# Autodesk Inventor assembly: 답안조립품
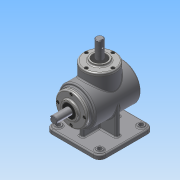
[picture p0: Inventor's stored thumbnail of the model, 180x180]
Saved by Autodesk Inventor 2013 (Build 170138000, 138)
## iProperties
Created: 2015-07
Part Number: 답안조립품
Document SubType Name: Assembly
Designer: ST1
Author: ST1
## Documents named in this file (14)
- C:\Users\ST1\Desktop\450705V1015\답안조립품.iam
- C:\Users\ST1\Desktop\450705V1015\1-본체..ipt
- C:\Users\ST1\Desktop\450705V1015\커버.ipt
- C:\Users\ST1\Desktop\450705V1015\베어링 6203.ipt
- C:\Users\ST1\Desktop\450705V1015\오일실.ipt
- C:\Users\ST1\Desktop\450705V1015\메인 축.ipt
- 메인 축.ipt
- C:\Users\ST1\Desktop\450705V1015\키 5x5.ipt
- C:\Users\ST1\Desktop\450705V1015\서브 축.ipt
- 서브 축.ipt
- C:\Users\ST1\Desktop\450705V1015\키 4x4.ipt
- C:\Users\ST1\Desktop\450705V1015\메인 베벨기어.ipt
- C:\Users\ST1\Desktop\450705V1015\서브 베벨기어.ipt
- C:\Users\ST1\Desktop\450705V1015\M4.ipt
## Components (9 placed, 2 different names)
1. 1-본체.:1
2. M4:1 — 각도:1
3. M4:2
4. M4:3
5. M4:4
6. M4:5 — 각도:2
7. M4:6
8. M4:7
9. M4:8
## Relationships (2: Angle 2)
- 각도:1 [Angle]: M4:1
- 각도:2 [Angle]: M4:5
